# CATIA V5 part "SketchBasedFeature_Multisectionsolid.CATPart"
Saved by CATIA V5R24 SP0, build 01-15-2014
Part number: Part16
Bounding box of the stored display mesh (mm): x -308 to 0, y -93.115 to 93.115, z 0 to 93.115
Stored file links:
  E:\Desktop_RNH\학부 CAD 수업 자료\[CAD_V2]강의자료(CAD)_2017년 이후\툴바예제\2 PartDesign\Upload2_1_modified\SketchBasedFeature_Multisectionsolid.CATPart

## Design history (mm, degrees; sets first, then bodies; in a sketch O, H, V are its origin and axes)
Body1 (main body)
  Sketch1 on yz-plane, origin (0, 0, 0), H (0, 1, 0), V (0, 0, 1)
    arc A1 centre (0, 0) radius 93.1148 from (93.1148, 0) to (-93.1148, 0) ccw
    line L1 (93.1148, 0) -> (-93.1148, 0)
    point P1 (93.1148, 0)
    coincidence: P1 H
    horizontal: L1 H
  Plane1: type Offset, RefPlane yz-plane, Offset -154
  Plane2: type Offset, RefPlane Plane1, Offset -154
  Sketch2 on Plane1, origin (-154, 0, 0), H (0, 1, 0), V (0, 0, 1)
    point P1 (92.8031, 0)
    line L1 (62.6134, 90.3932) -> (-53.2934, 90.3932)
    point P4 (-92.1086, 0)
    line L2 (-92.1086, 0) -> (92.8031, 0)
    line L3 (92.8031, 0) -> (82.8808, 50.5749)
    line L4 (82.8808, 50.5749) -> (62.6134, 90.3932)
    line L5 (-53.2934, 90.3932) -> (-78.3104, 58.6654)
    line L6 (-78.3104, 58.6654) -> (-92.1086, 0)
    coincidence: P1 H, P4 H
    horizontal: L1 H, L2 H
  Sketch3 on Plane2, origin (-308, 0, 0), H (0, 1, 0), V (0, 0, 1)
    point P1 (92.0965, 0)
    line L1 (92.0965, 0) -> (-92.4679, 0)
    line L2 (-92.4679, 0) -> (-92.4679, 91.9476)
    line L3 (-92.4679, 91.9476) -> (92.0965, 91.9476)
    line L4 (92.0965, 91.9476) -> (92.0965, 0)
    coincidence: P1 H
    horizontal: L1 H, L3 H
    vertical: L2 V, L4 V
